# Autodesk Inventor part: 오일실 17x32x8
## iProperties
IsCustomPart: 1
Created: 2009-02
Part Number: 오일실 17x32x8
Material: 고무
Description: 오일-실
Document SubType Name: Modeling
Standard: KS B 2804
Designer: 한국산업디자인학원
Standards Organization: KS
Language: ko-KR
Size Designation: D - 17 32 8
Categories: <MemberInstance><Categories><Category DisplayName="샤프트 부품" InternalName="7f7aeb1f-a693-4053-b835-cee3144e0d98" Mnemonic="SHFT"><Category DisplayName="실링" Intern
Density: 0.93 g/cm^3
Author: 한국산업디자인학원
